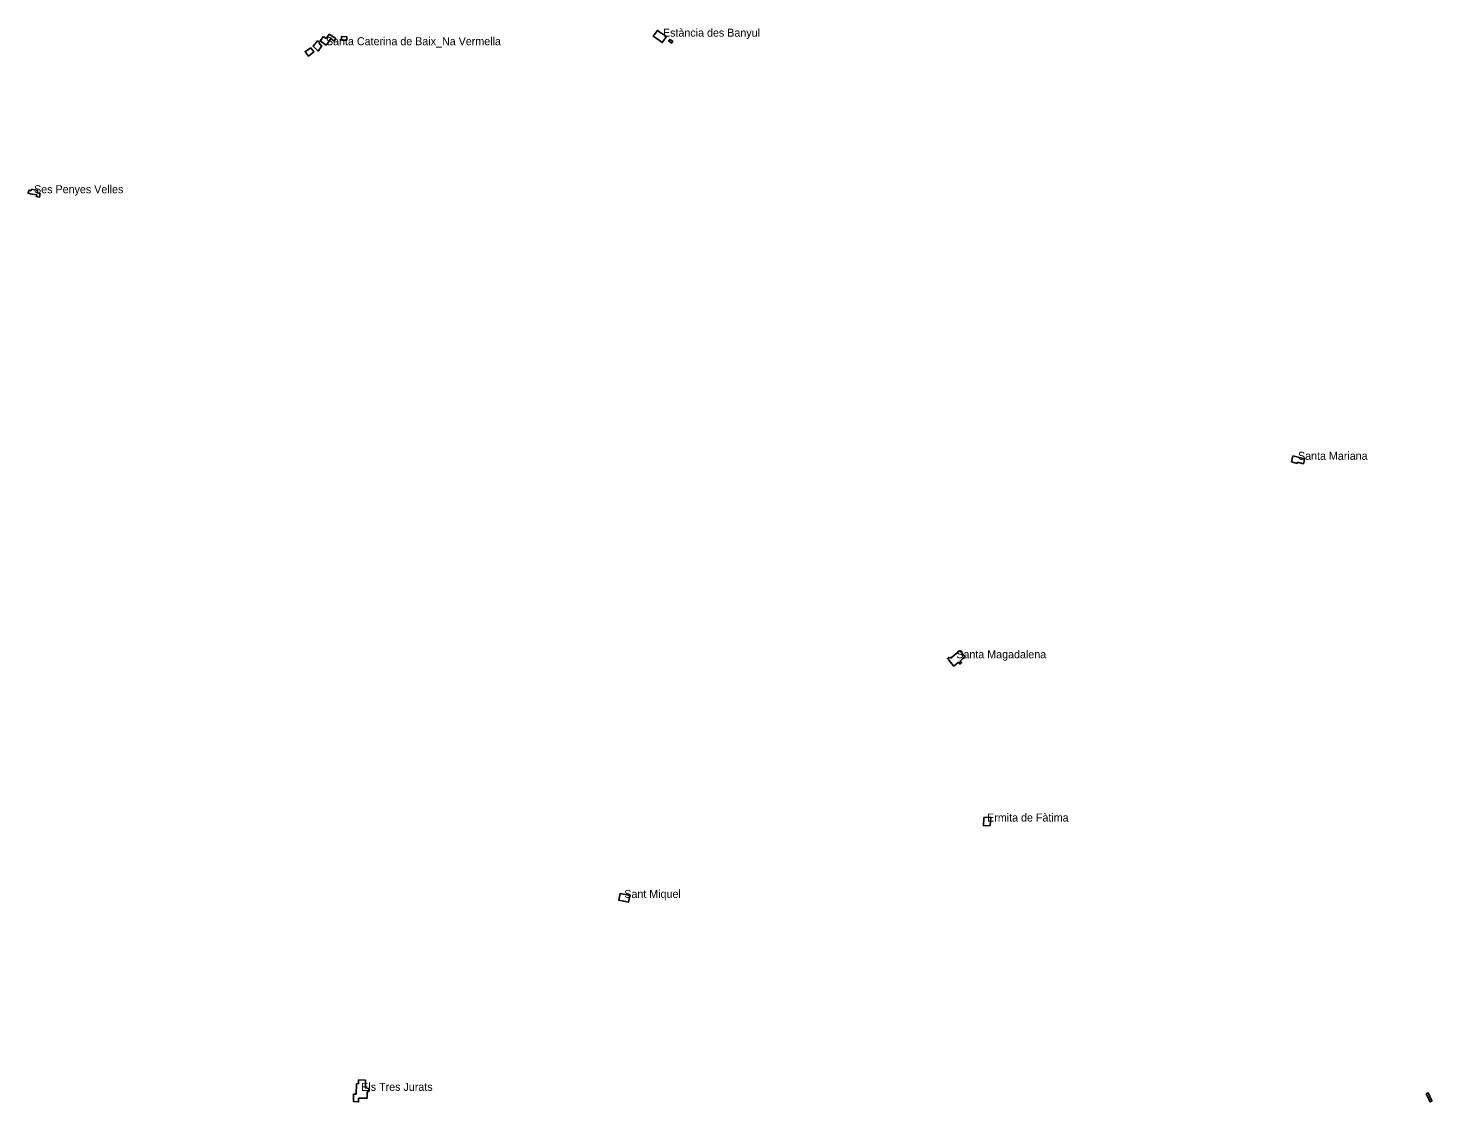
# Model space of a CAD drawing. Extents: x 599451 to 612034, y 4411179 to 4428219.
# Drawn here: x 602786 to 604890, y 4421926 to 4423535 of the extents above; entities that cross this region are included whole.
import ezdxf

# ---------------------------------------------------------------- set-up
doc = ezdxf.new("R2010")
doc.units = 0
doc.layers.add('Bé Arquitectònic', color=7, linetype='Continuous')

msp = doc.modelspace()

# ---------------------------------------------------------------- linework, layer by layer
at = {"layer": 'Bé Arquitectònic'}
for points in [[(603733.4, 4423529.1), (603729, 4423532.1), (603722.7, 4423523.3), (603727.2, 4423520.2), (603732, 4423516.9), (603736.4, 4423513.8), (603742.6, 4423522.7), (603738.2, 4423525.7)], [(603223.2, 4423513.5), (603219.6, 4423516.2), (603212.8, 4423508.2), (603220.6, 4423501.1), (603225.8, 4423509.1), (603222.2, 4423512.1)], [(603228.3, 4423523), (603223.5, 4423516.2), (603232.6, 4423510), (603233.8, 4423511.4), (603237.7, 4423517.1), (603239.5, 4423519.7), (603244.7, 4423516), (603247, 4423519.7), (603237.1, 4423526.3), (603232.9, 4423520.2), (603232.7, 4423520), (603228.4, 4423522.9)], [(603262.2, 4423517.4), (603263.4, 4423517.4), (603263.4, 4423522.6), (603255.7, 4423523.1), (603255.7, 4423522), (603255.5, 4423517.6)], [(603746.1, 4423516.2), (603746, 4423516), (603750.5, 4423513.1), (603750.7, 4423513.3), (603752.1, 4423515.7), (603747.6, 4423518.5)], [(603209.3, 4423505.9), (603208.7, 4423505.4), (603201, 4423499.9), (603201.5, 4423499.2), (603205.8, 4423493.4), (603208.7, 4423495.6), (603214, 4423499.7)], [(602790.4, 4423291.6), (602786.6, 4423292.4), (602785.7, 4423288), (602786.2, 4423287.9), (602789.5, 4423287.2), (602798.1, 4423285.5), (602798.6, 4423285.4), (602798.1, 4423283), (602802.1, 4423282.2), (602802.6, 4423282.1), (602803.7, 4423287.3), (602803.2, 4423287.4), (602799.2, 4423288.3), (602799.9, 4423291.8), (602790.8, 4423293.8)], [(604679.4, 4422885.1), (604688.3, 4422883), (604688.7, 4422884.6), (604697.5, 4422882.4), (604698.4, 4422886.4), (604699.3, 4422889.8), (604681.7, 4422894.1)], [(604180.4, 4422584.8), (604182.8, 4422582), (604185.1, 4422583.9), (604182.7, 4422586.7), (604186.5, 4422589.9), (604190.3, 4422593), (604182.5, 4422602.4), (604181.3, 4422601.4), (604178.6, 4422599.2), (604172.9, 4422594.3), (604169, 4422591), (604167.9, 4422592.3), (604166.3, 4422591.1), (604165.5, 4422592), (604163.9, 4422590.7), (604165.8, 4422588.3), (604168.1, 4422585.6), (604173.5, 4422579.1)], [(604227.9, 4422340.1), (604228.7, 4422352.4), (604218.4, 4422351.9), (604217.9, 4422339.8)], [(603680.7, 4422236.5), (603673.2, 4422238.1), (603671.1, 4422228.2), (603678.7, 4422226.6), (603685.6, 4422225.2), (603687.6, 4422235.1)], [(603273.7, 4421926.2), (603281.2, 4421925.9), (603281.2, 4421931.4), (603293.8, 4421931.4), (603294, 4421941.1), (603296.5, 4421941.3), (603296.3, 4421946), (603291.3, 4421946.7), (603291.5, 4421958.4), (603281.2, 4421958.9), (603281.2, 4421953.2), (603277.8, 4421952.8), (603277.3, 4421937.5), (603273.7, 4421937.5)], [(604883.8, 4421933.3), (604886.9, 4421926.5), (604887.2, 4421925.8), (604890.1, 4421927.1), (604889.9, 4421927.6), (604884.6, 4421939.4), (604882.1, 4421938.2), (604881.7, 4421938.1)]]:
    msp.add_lwpolyline(points, close=True, dxfattribs=at)

# ---------------------------------------------------------------- texts
for s, p in [('Estància des Banyul', (603737.4, 4423522.6)), ('Santa Caterina de Baix_Na Vermella', (603232.2, 4423509.8)), ('Ses Penyes Velles', (602794.7, 4423287.9)), ('Santa Mariana', (604689.3, 4422888.3)), ('Santa Magadalena', (604177.1, 4422590.8)), ('Ermita de Fàtima', (604223.3, 4422346.1)), ('Sant Miquel', (603679.4, 4422231.6)), ('Els Tres Jurats', (603285.1, 4421942.4))]:
    msp.add_text(s, height=12, dxfattribs=at).set_placement(p)

doc.saveas('drawing.dxf')
